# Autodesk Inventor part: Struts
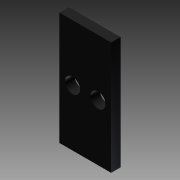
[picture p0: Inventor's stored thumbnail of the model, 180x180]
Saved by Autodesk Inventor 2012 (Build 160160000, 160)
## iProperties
Created: 2014-02
Part Number: Struts
Material: Default
Document SubType Name: Modeling
Designer: Aser
Density: 1 g/cm^3
Author: Aser
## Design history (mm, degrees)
sketch "Sketch1"
  geometry: L1 (0, 0)-(55, 0); L2 (55, 0)-(55, 120); L3 (55, 120)-(0, 120); L4 (0, 120)-(0, 0)
  constraints: 8 end point, 2 parallel, 1 horizontal, 1 perpendicular
  dimensions: "d0" = 55 distance of L3.end L2.end; "d1" = 120 distance of L2.end L1.end
extrude "Extrusion1" new body sketch "Sketch1" distance "d2" = 10; taper "d3" = 0 deg
sketch "Sketch2"
  geometry: L1 (55, 120)-(55, 0) reference; L2 (0, 120)-(55, 120) reference; C1 r 8 at (14, 60); C2 r 8 at (41, 60)
  constraints: 2 centre point
  dimensions: "d4" = 16 diameter of C1; "d5" = 16 diameter of C2; "d6" = 27 distance of C2.centre C1.centre; "d7" = 14 distance from line of L1 C2.centre; "d8" = 60 distance from line of L2 C1.centre; "d9" = 60 distance from line of L2 C2.centre (= d8)
extrude "Extrusion2" cut sketch "Sketch2" distance "d10" = 10; taper "d11" = 0 deg
body "Solid1"
